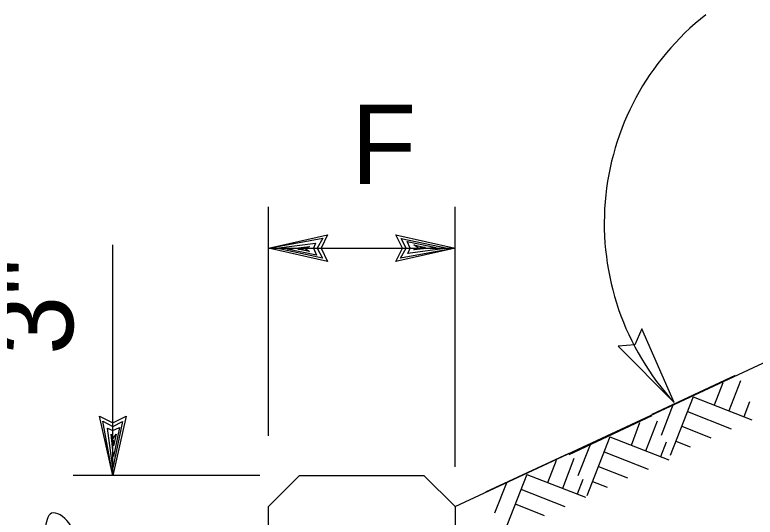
# Model space of a CAD drawing. Extents: x -0.08 to 2.83, y -0.03 to 1.92.
# Drawn here: x 1.7489 to 1.8705, y 0.7273 to 0.8098 of the extents above; entities that cross this region are included whole.
import ezdxf

# ---------------------------------------------------------------- set-up
doc = ezdxf.new("R2010")
doc.units = 0
for name, color, linetype in [('5', 7, 'Continuous'), ('50', 7, 'Continuous'), ('54', 7, 'Continuous'), ('55', 7, 'Continuous'), ('57', 7, 'Continuous')]:
    doc.layers.add(name, color=color, linetype=linetype)

msp = doc.modelspace()

# ---------------------------------------------------------------- linework, layer by layer
at = {"layer": '5'}
for p, q in [((1.8212335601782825, 0.7290622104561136), (1.884991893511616, 0.7587872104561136)), ((1.8536252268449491, 0.7442043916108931), (1.8672918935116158, 0.7506043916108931)), ((1.8651918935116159, 0.7493710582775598), (1.8637918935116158, 0.7457043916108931)), ((1.8680918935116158, 0.7496710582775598), (1.8661918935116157, 0.7447377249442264)), ((1.860325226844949, 0.7470710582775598), (1.8565585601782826, 0.7374043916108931)), ((1.860325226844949, 0.7470710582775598), (1.8699918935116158, 0.7433043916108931)), ((1.8570585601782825, 0.7458377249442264), (1.8550585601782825, 0.7407043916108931)), ((1.8695585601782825, 0.7462377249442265), (1.8686252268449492, 0.7438043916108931)), ((1.8593918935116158, 0.7446710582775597), (1.866591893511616, 0.7418043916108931)), ((1.8399585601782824, 0.7376049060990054), (1.8536252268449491, 0.7439715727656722)), ((1.8544252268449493, 0.7430715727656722), (1.8525252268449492, 0.7381382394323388)), ((1.8515252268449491, 0.7427715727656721), (1.850125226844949, 0.7390715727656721)), ((1.8584585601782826, 0.7422377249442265), (1.8632585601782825, 0.7403377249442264)), ((1.8466585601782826, 0.7404715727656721), (1.8428918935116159, 0.7308049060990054)), ((1.8466585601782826, 0.7404715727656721), (1.856325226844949, 0.7367049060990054)), ((1.8433918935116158, 0.7392049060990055), (1.8413918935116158, 0.7341049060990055)), ((1.8558918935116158, 0.7396049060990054), (1.8549585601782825, 0.7372049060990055)), ((1.8574918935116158, 0.7397710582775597), (1.8598585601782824, 0.7388377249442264)), ((1.845725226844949, 0.7380382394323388), (1.8529252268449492, 0.7352049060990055)), ((1.826291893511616, 0.7314710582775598), (1.8399585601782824, 0.7378377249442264)), ((1.8407585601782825, 0.7369377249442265), (1.8388585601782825, 0.7320043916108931)), ((1.8378585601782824, 0.7366377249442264), (1.8364252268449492, 0.7329377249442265)), ((1.8447918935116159, 0.7356382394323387), (1.8495585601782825, 0.7337382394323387)), ((1.8329918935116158, 0.7343377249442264), (1.8292252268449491, 0.7246710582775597)), ((1.8329918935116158, 0.7343377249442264), (1.8426585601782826, 0.7305710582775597)), ((1.842225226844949, 0.7334710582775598), (1.8412585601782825, 0.7310710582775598)), ((1.843825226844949, 0.7331715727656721), (1.8461918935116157, 0.7322382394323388)), ((1.829725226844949, 0.7330710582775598), (1.827725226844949, 0.7279710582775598)), ((1.8320585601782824, 0.7319043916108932), (1.8392585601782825, 0.7290710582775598)), ((1.8310918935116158, 0.7295043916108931), (1.8358918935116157, 0.7276043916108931))]:
    msp.add_line(p, q, dxfattribs=at)
at = {"layer": '50'}
for p, q in [((1.790580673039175, 0.7290622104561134), (1.7956889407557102, 0.7341573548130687)), ((1.7956889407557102, 0.7341573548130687), (1.8161285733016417, 0.7341573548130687)), ((1.8161285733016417, 0.7341573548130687), (1.8212335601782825, 0.7290622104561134)), ((1.790580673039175, 0.37751693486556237), (1.790580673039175, 0.7290622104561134)), ((1.8212335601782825, 0.7290622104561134), (1.8212335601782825, 0.37751693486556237))]:
    msp.add_line(p, q, dxfattribs=at)
at = {"layer": '54'}
msp.add_lwpolyline([(1.857214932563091, 0.74611824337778), (1.851881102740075, 0.7582002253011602), (1.8507636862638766, 0.7556181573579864), (1.848015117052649, 0.7553935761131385)], close=True, dxfattribs=at)
at = {"layer": '55'}
for p, q in [((1.790580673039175, 0.7406677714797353), (1.790580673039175, 0.7782533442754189)), ((1.8212335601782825, 0.73557262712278), (1.8212335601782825, 0.7782533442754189)), ((1.790580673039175, 0.7714637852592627), (1.8002919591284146, 0.7736553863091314)), ((1.8002919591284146, 0.7736553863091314), (1.79923552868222, 0.7714637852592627)), ((1.8125787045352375, 0.7714637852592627), (1.811522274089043, 0.7736357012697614)), ((1.811522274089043, 0.7736357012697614), (1.8212335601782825, 0.7714637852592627)), ((1.790580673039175, 0.7714637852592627), (1.799517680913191, 0.7730910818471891)), ((1.79184707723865, 0.7714637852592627), (1.7983234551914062, 0.7723135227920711)), ((1.7983234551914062, 0.7723135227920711), (1.7979724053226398, 0.7714637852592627)), ((1.799517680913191, 0.7730910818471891), (1.7986023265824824, 0.7714637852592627)), ((1.813211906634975, 0.7714637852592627), (1.812368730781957, 0.7730779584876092)), ((1.812368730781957, 0.7730779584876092), (1.8199671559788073, 0.7714637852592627)), ((1.8138418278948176, 0.7714637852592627), (1.813349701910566, 0.7725825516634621)), ((1.813349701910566, 0.7725825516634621), (1.81813644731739, 0.7715982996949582)), ((1.7650327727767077, 0.7341573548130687), (1.7650327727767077, 0.7719936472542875)), ((1.8002919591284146, 0.7692918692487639), (1.790580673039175, 0.7714637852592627)), ((1.790580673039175, 0.7714637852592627), (1.8212335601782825, 0.7714637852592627)), ((1.7994455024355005, 0.7698496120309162), (1.79184707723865, 0.7714637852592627)), ((1.7936777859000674, 0.771329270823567), (1.7973359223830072, 0.7717557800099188)), ((1.7984645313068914, 0.770345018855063), (1.7936777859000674, 0.771329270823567)), ((1.7973359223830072, 0.7709126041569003), (1.7954363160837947, 0.771329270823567)), ((1.7954363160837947, 0.771329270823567), (1.7963549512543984, 0.771329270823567)), ((1.7973359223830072, 0.7717557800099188), (1.7966338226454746, 0.7714014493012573)), ((1.7966338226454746, 0.7714014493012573), (1.7973359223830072, 0.7709126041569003)), ((1.7979724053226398, 0.7714637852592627), (1.7984645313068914, 0.770345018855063)), ((1.7986023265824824, 0.7714637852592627), (1.7994455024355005, 0.7698496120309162)), ((1.79923552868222, 0.7714637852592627), (1.8002919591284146, 0.7692918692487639)), ((1.8212335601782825, 0.7714637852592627), (1.811522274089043, 0.7692721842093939)), ((1.811522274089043, 0.7692721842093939), (1.8125787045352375, 0.7714637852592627)), ((1.8212335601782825, 0.7714637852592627), (1.8122965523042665, 0.7698364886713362)), ((1.8122965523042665, 0.7698364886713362), (1.813211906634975, 0.7714637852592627)), ((1.8199671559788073, 0.7714637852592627), (1.8134907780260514, 0.7706140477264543)), ((1.8134907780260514, 0.7706140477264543), (1.8138418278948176, 0.7714637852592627)), ((1.8151804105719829, 0.7715261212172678), (1.8144783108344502, 0.7720149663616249)), ((1.8144783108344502, 0.7720149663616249), (1.8163779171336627, 0.7715982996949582)), ((1.81813644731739, 0.7715982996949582), (1.8144783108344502, 0.7711717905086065)), ((1.8144783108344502, 0.7711717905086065), (1.8151804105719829, 0.7715261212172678)), ((1.8163779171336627, 0.7715982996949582), (1.815459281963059, 0.7715982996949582)), ((1.7650327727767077, 0.7341573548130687), (1.7628411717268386, 0.7438686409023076)), ((1.7628411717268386, 0.7438686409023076), (1.7650327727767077, 0.7428122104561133)), ((1.7650327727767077, 0.7341573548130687), (1.763405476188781, 0.7430943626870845)), ((1.763405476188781, 0.7430943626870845), (1.7650327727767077, 0.7421790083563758)), ((1.7650327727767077, 0.7428122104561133), (1.7672046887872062, 0.7438686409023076)), ((1.7672046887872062, 0.7438686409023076), (1.7650327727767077, 0.7341573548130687)), ((1.7650327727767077, 0.7421790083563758), (1.7666469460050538, 0.7430221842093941)), ((1.7666469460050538, 0.7430221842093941), (1.7650327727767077, 0.7354237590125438)), ((1.7650327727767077, 0.7354237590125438), (1.7641830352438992, 0.7419001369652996)), ((1.7641830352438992, 0.7419001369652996), (1.7650327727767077, 0.7415490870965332)), ((1.7650327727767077, 0.7415490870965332), (1.766151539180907, 0.7420412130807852)), ((1.766151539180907, 0.7420412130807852), (1.7651672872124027, 0.7372544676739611)), ((1.7651672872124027, 0.7372544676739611), (1.7647407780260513, 0.7409126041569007)), ((1.7647407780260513, 0.7409126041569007), (1.7650951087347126, 0.740210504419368)), ((1.7650951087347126, 0.740210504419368), (1.7655839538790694, 0.7409126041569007)), ((1.7655839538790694, 0.7409126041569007), (1.7651672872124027, 0.7390129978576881)), ((1.7651672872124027, 0.7390129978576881), (1.7651672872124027, 0.7399316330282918)), ((1.7891785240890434, 0.7341573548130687), (1.758522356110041, 0.7341573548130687))]:
    msp.add_line(p, q, dxfattribs=at)
msp.add_arc((1.889198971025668, 0.775554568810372), 0.04346810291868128, 128.0620969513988, 222.62473614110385, dxfattribs=at)
msp.add_spline([(1.7284865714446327, 0.7214544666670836), (1.7316001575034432, 0.7214544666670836), (1.7373083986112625, 0.7201571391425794), (1.7476870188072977, 0.7180814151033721), (1.755989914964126, 0.7191192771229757), (1.7585845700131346, 0.7222328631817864), (1.7578061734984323, 0.7263843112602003), (1.7549520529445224, 0.7279411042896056), (1.7539141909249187, 0.7253464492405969), (1.7539141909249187, 0.7224923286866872), (1.7570277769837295, 0.716524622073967)], degree=3, dxfattribs=at)

# ---------------------------------------------------------------- texts
at = {"layer": '57'}
msp.add_text('F', height=0.013020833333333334, dxfattribs=at).set_placement((1.8042107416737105, 0.7820201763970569))
msp.add_text('3"', height=0.013020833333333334, rotation=90, dxfattribs=at).set_placement((1.758522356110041, 0.7539500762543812))

doc.saveas('drawing.dxf')
